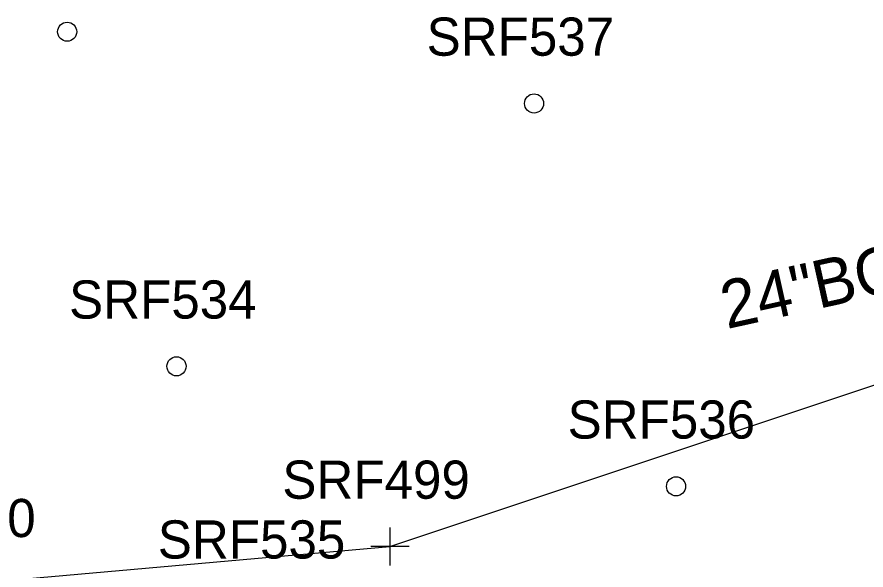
# Model space of a CAD drawing. Extents: x 818717 to 846077, y 440014 to 541392.
# Drawn here: x 831333.4 to 831422.3, y 493076.2 to 493134.2 of the extents above; entities that cross this region are included whole.
import ezdxf

# ---------------------------------------------------------------- set-up
doc = ezdxf.new("R2010")
doc.units = 0
for name, color, linetype in [('SURVEY - CENTERLINE - Preliminary', 7, 'Continuous'), ('SURVEY - DTM - Spot Points - Locators', 7, 'Continuous'), ('SURVEY - DTM - Spot Points - Point Numbers', 7, 'Continuous'), ('SURVEY - PROPERTY - ROW Lines', 7, 'Continuous'), ('SURVEY - VEGETATION - Features - Points - Locators', 7, 'Continuous'), ('SURVEY - VEGETATION - Features - Points - Numbers', 7, 'Continuous'), ('SURVEY - VEGETATION - Features with Text', 7, 'Continuous')]:
    doc.layers.add(name, color=color, linetype=linetype)

msp = doc.modelspace()

# ---------------------------------------------------------------- linework, layer by layer
at = {"layer": 'SURVEY - CENTERLINE - Preliminary'}
msp.add_arc((818719.062, 541389.917), 50000, 284.7154065, 285.0436538, dxfattribs=at)
msp.add_arc((818719.062, 541389.917), 50000, 284.7154065, 285.0436538, dxfattribs=at)
msp.add_arc((818719.062, 541389.917), 50000, 284.7154065, 285.0436538, dxfattribs=at)
msp.add_arc((818719.062, 541389.917), 50000, 284.7154065, 285.0436538, dxfattribs=at)
at = {"layer": 'SURVEY - DTM - Spot Points - Locators'}
for centre in [(831338.684, 493132.612), (831387.535, 493125.099), (831350.123, 493097.565), (831402.396, 493084.994)]:
    msp.add_circle(centre, 1, dxfattribs=at)
at = {"layer": 'SURVEY - PROPERTY - ROW Lines'}
msp.add_arc((818719.062, 541389.917), 49970, 284.7154008, 285.0436538, dxfattribs=at)
at = {"layer": 'SURVEY - VEGETATION - Features - Points - Locators'}
for p, q in [((831372.452, 493080.695), (831372.452, 493076.695)), ((831374.452, 493078.695), (831370.452, 493078.695))]:
    msp.add_line(p, q, dxfattribs=at)
at = {"layer": 'SURVEY - VEGETATION - Features with Text'}
msp.add_lwpolyline([(831133.174, 493025.253), (831188.614, 493039.111), (831273.803, 493058.132), (831327.178, 493074.676), (831372.452, 493078.695), (831446.522, 493103.398), (831511.696, 493128.914), (831543.941, 493118.924), (831551.053, 493086.403), (831538.719, 493077.69), (831488.182, 493059.708), (831414.149, 493041.529), (831340.276, 493029.597), (831322.827, 493014.847), (831277.91, 493002.895), (831227.538, 492995.396), (831165.974, 492983.974)], dxfattribs=at)

# ---------------------------------------------------------------- texts
at = {"layer": 'SURVEY - DTM - Spot Points - Point Numbers'}
for s, p in [('SRF537', (831376.295, 493130.099)), ('SRF534', (831338.884, 493102.565)), ('SRF536', (831391.046, 493089.994)), ('SRF535', (831348.166, 493077.431))]:
    msp.add_text(s, height=4, dxfattribs=at).set_placement(p)
at = {"layer": 'SURVEY - VEGETATION - Features - Points - Numbers'}
for s, p in [('SRF499', (831361.197, 493083.695)), ('SRF500', (831315.765, 493079.676))]:
    msp.add_text(s, height=4, dxfattribs=at).set_placement(p)
at = {"layer": 'SURVEY - VEGETATION - Features with Text'}
msp.add_text('24"BOX ELDER', height=5, rotation=12.453, dxfattribs=at).set_placement((831407.702, 493101.458))

doc.saveas('drawing.dxf')
